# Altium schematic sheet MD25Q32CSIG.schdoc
size 127 x 101 mm
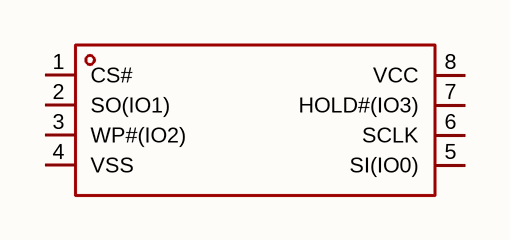
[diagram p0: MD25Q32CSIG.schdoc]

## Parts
U?  md25q32csig  [SOP-8_L5.3-W5.2-P1.27-LS7.9-BL]  (value not drawn)

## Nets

Not connected (* = marked no-connect by the designer): U? 1(CS#) 2(SO(IO1)) 3(WP#(IO2)) 4(VSS) 5(SI(IO0)) 6(SCLK) 7(HOLD#(IO3)) 8(VCC)

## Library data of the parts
U? = md25q32csig: 接口类型:SPI;存储容量:32Mbit;时钟频率(fc):120MHz;; Manufacturer: GigaDevice(兆易创新); AddInBom: yes; ModelId: b3bace262c53465a9e6115a2e0c7b3cc; ModelTransform: 205.905,311.023,0,0,0,0,0,0,0; Interface: SPI; Memory Size: 32Mbit; Clock Frequency: 120MHz; Voltage - Supply: 2.7V~3.6V; Standby Supply Current: 5uA; Program / Erase Cycles: 100000次; Page Programming Time (Tpp): 700us; Block Erase Time(tBE): 300ms@(64KB); Data Retention - TDR (Year): 20年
